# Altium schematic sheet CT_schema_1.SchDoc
size 471 x 395 mm
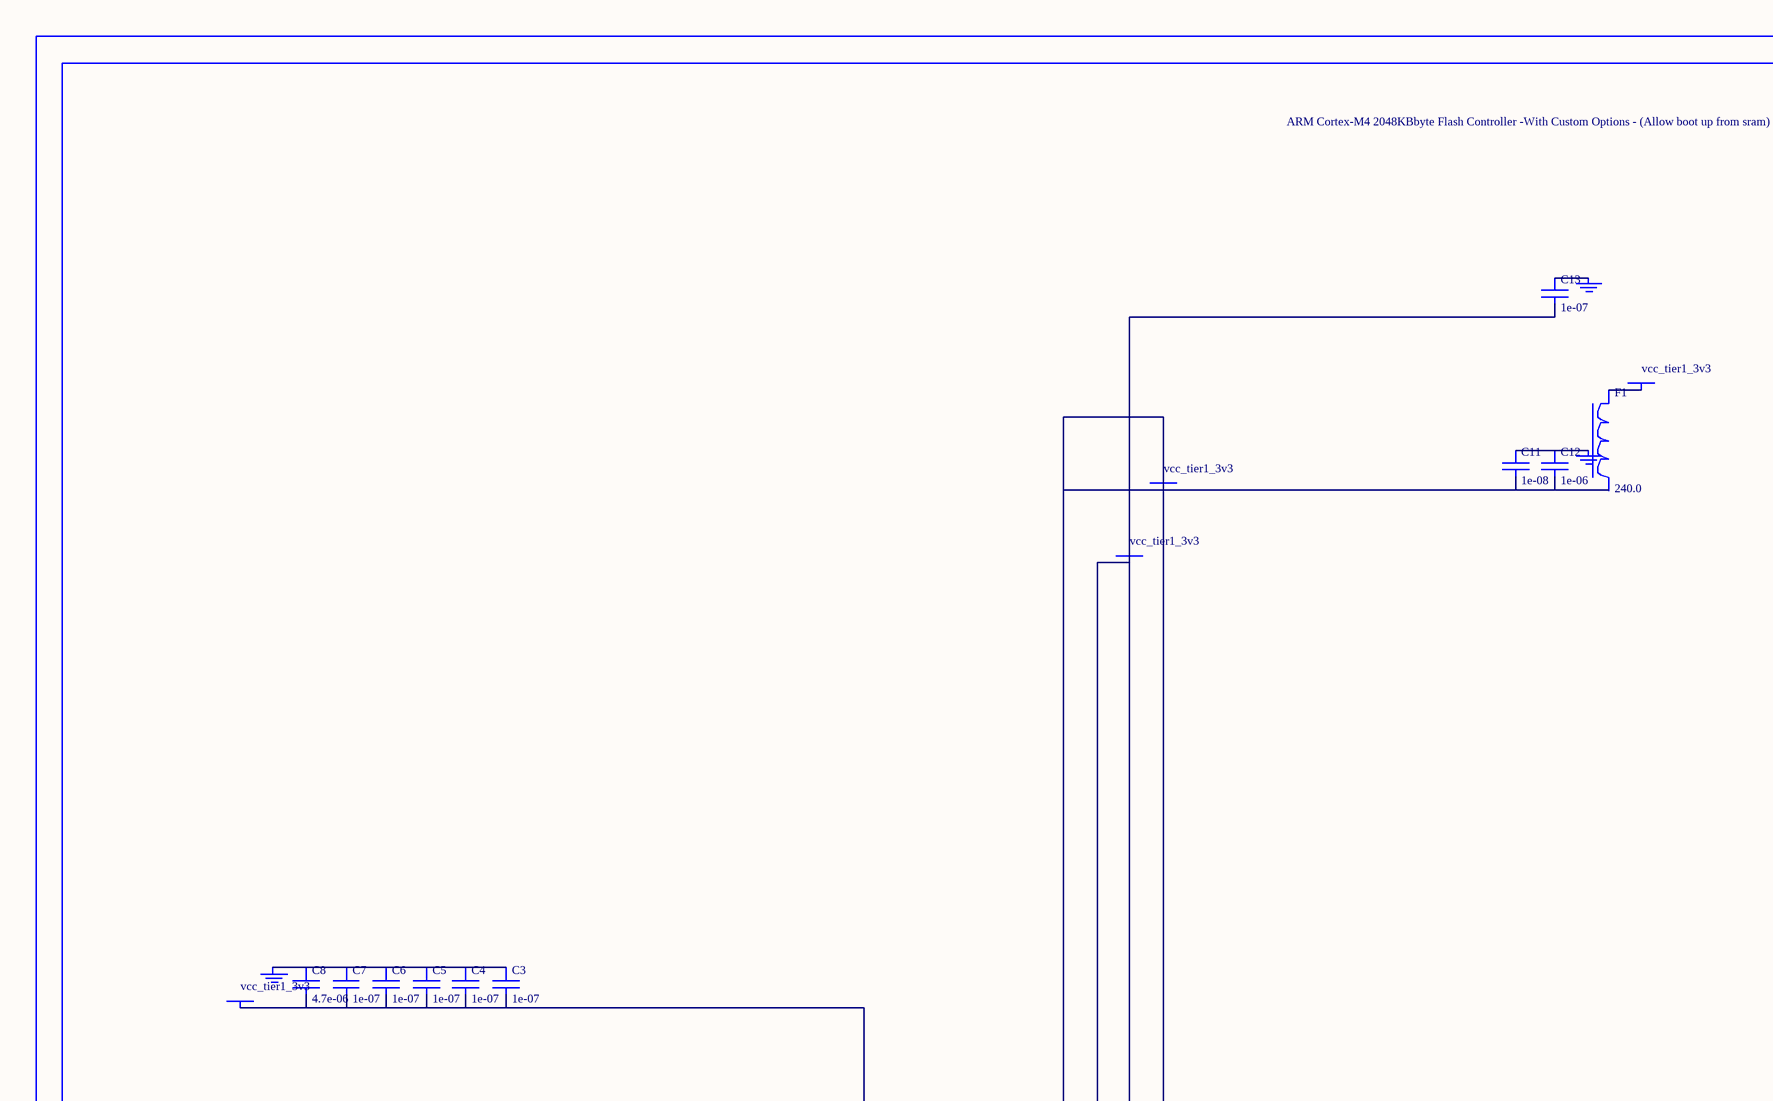
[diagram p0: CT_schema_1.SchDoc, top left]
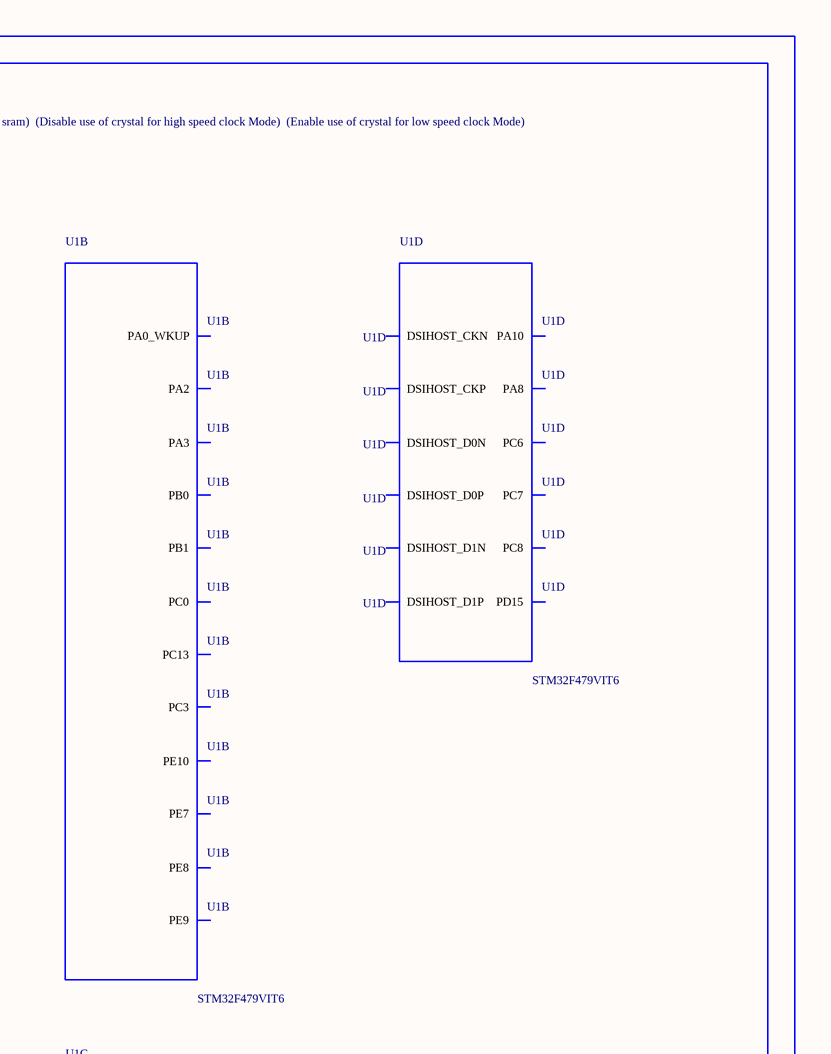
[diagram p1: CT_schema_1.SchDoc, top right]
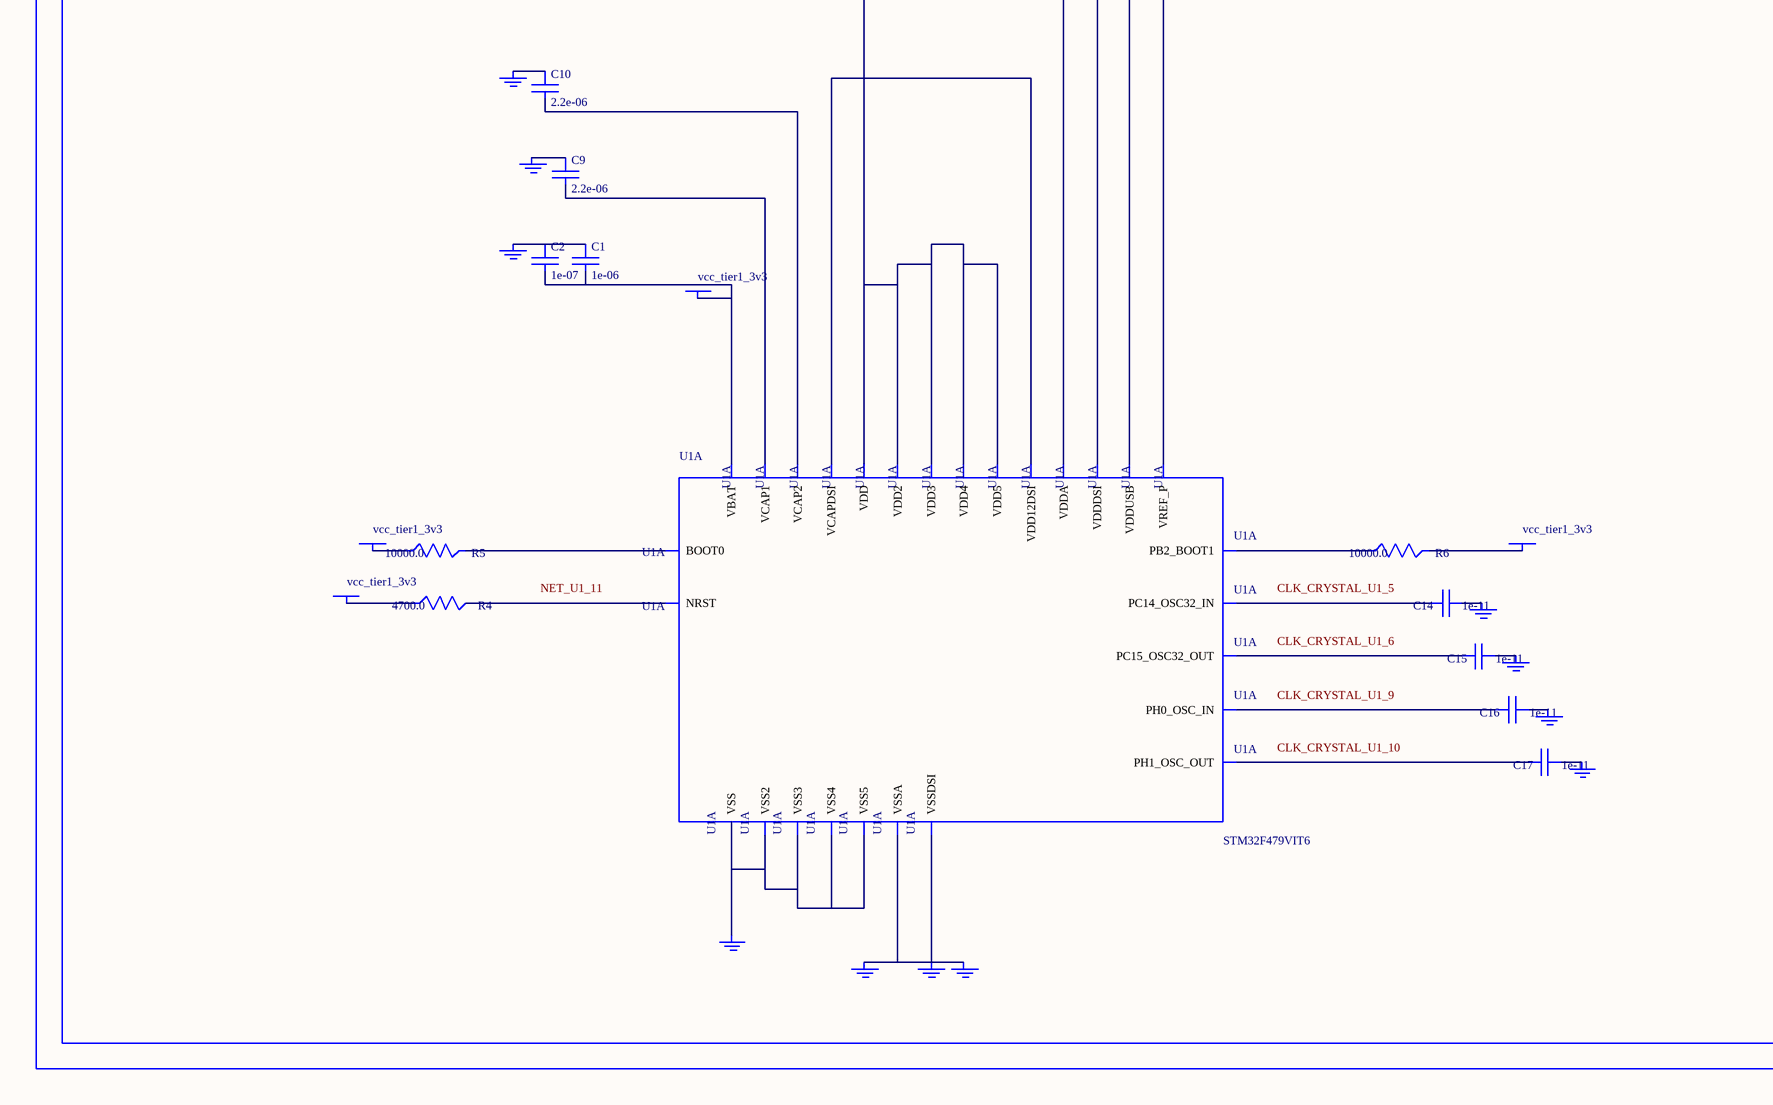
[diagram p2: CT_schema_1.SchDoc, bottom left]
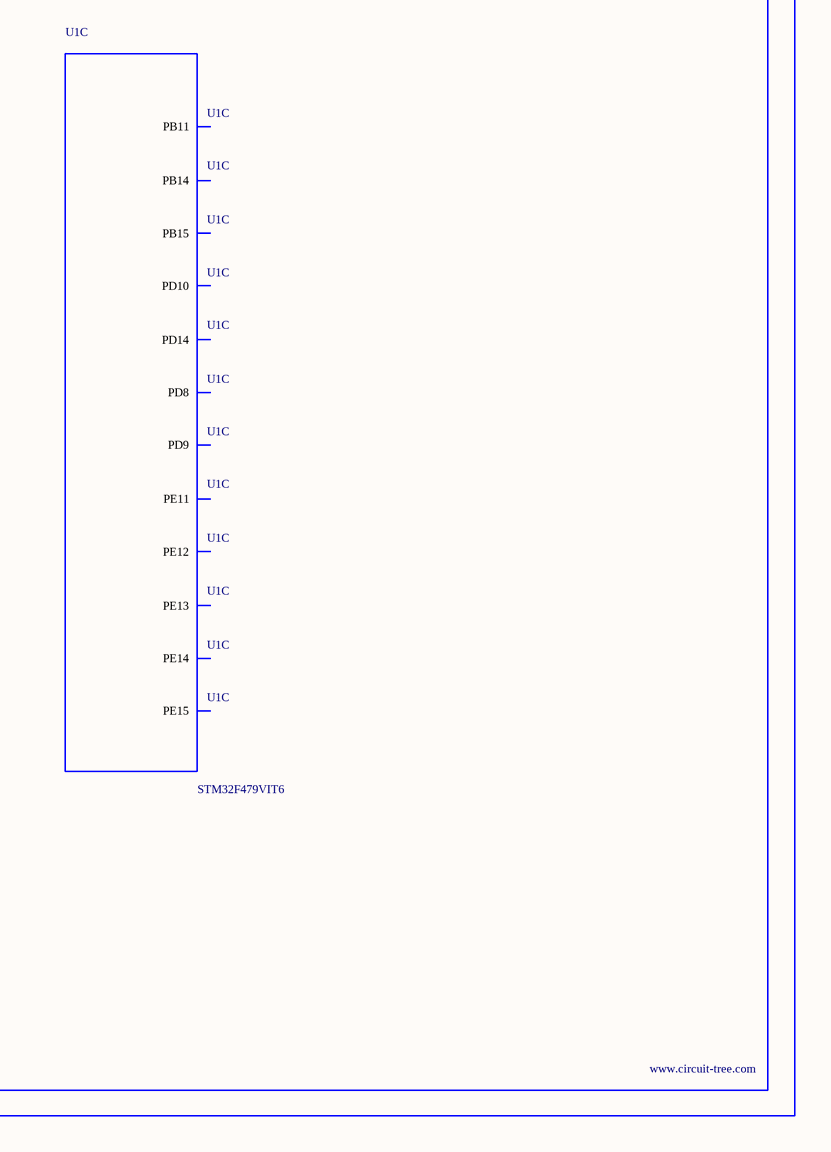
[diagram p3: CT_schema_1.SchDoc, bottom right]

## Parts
BORDER0  (no value)
C1  1e-06  [C0603]
C2  1e-07  [C0603]
C3  1e-07  [C0603]
C4  1e-07  [C0603]
C5  1e-07  [C0603]
C6  1e-07  [C0603]
C7  1e-07  [C0603]
C8  4.7e-06  [C0603]
C9  2.2e-06  [C0603]
C10  2.2e-06  [C0603]
C11  1e-08  [C0603]
C12  1e-06  [C0603]
C13  1e-07  [C0603]
C14  1e-11  [C0402]
C15  1e-11  [C0402]
C16  1e-11  [C0402]
C17  1e-11  [C0402]
F1  240.0  [L0603]
GND_INSTANCE_0_0  (no value)
GND_INSTANCE_0_1  (no value)
GND_INSTANCE_0_2  (no value)
GND_INSTANCE_0_3  (no value)
GND_INSTANCE_0_4  (no value)
GND_INSTANCE_0_5  (no value)
GND_INSTANCE_0_6  (no value)
GND_INSTANCE_0_7  (no value)
GND_INSTANCE_0_8  (no value)
GND_INSTANCE_0_9  (no value)
GND_INSTANCE_0_10  (no value)
GND_INSTANCE_0_11  (no value)
GND_INSTANCE_0_12  (no value)
GND_INSTANCE_0_13  (no value)
POWER_INSTANCE_0_0  vcc_tier1_3v3
POWER_INSTANCE_0_1  vcc_tier1_3v3
POWER_INSTANCE_0_2  vcc_tier1_3v3
POWER_INSTANCE_0_3  vcc_tier1_3v3
POWER_INSTANCE_0_4  vcc_tier1_3v3
POWER_INSTANCE_0_5  vcc_tier1_3v3
POWER_INSTANCE_0_6  vcc_tier1_3v3
POWER_INSTANCE_0_7  vcc_tier1_3v3
R4  4700.0  [R0603]
R5  10000.0  [R0603]
R6  10000.0  [R0603]
U1  STM32F479VIT6  [LQFP100]  (parts A,B,C,D of 9)

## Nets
NetC1_1: C1.1 C2.1 GND_INSTANCE_0_0.0(GND)
NetC1_2: C1.2 C2.2 POWER_INSTANCE_0_0.0(PWR) U1.3(VBAT)
NetC3_1: C3.1 C4.1 C5.1 C6.1 C7.1 C8.1 GND_INSTANCE_0_3.0(GND)
NetC3_2: C3.2 C4.2 C5.2 C6.2 C7.2 C8.2 POWER_INSTANCE_0_1.0(PWR) U1.8(VDD) U1.24(VDD2) U1.45(VDD3) U1.77(VDD4) U1.100(VDD5)
NetC9_1: C9.1 GND_INSTANCE_0_8.0(GND)
NetC9_2: C9.2 U1.43(VCAP1)
NetC10_1: C10.1 GND_INSTANCE_0_12.0(GND)
NetC10_2: C10.2 U1.76(VCAP2)
NetC11_1: C11.1 C12.1 GND_INSTANCE_0_7.0(GND)
NetC11_2: C11.2 C12.2 C13.2 POWER_INSTANCE_0_4.0(PWR) POWER_INSTANCE_0_5.0(PWR) U1.17(VREF_P) U1.18(VDDA) U1.55(VDDDSI) U1.65(VDDUSB)
NetC13_1: C13.1 GND_INSTANCE_0_11.0(GND)
NetC14_1: C14.1 GND_INSTANCE_0_1.0(GND)
NetC14_2: C14.2 U1.5(PC14_OSC32_IN)
NetC15_1: C15.1 GND_INSTANCE_0_2.0(GND)
NetC15_2: C15.2 U1.6(PC15_OSC32_OUT)
NetC16_1: C16.1 GND_INSTANCE_0_4.0(GND)
NetC16_2: C16.2 U1.9(PH0_OSC_IN)
NetC17_1: C17.1 GND_INSTANCE_0_5.0(GND)
NetC17_2: C17.2 U1.10(PH1_OSC_OUT)
NetF1_1: F1.1 POWER_INSTANCE_0_2.0(PWR)
NetGND_INSTANCE_0_6_0: GND_INSTANCE_0_6.0(GND) GND_INSTANCE_0_9.0(GND) GND_INSTANCE_0_10.0(GND) U1.16(VSSA) U1.59(VSSDSI)
NetGND_INSTANCE_0_13_0: GND_INSTANCE_0_13.0(GND) U1.2(VSS) U1.7(VSS2) U1.23(VSS3) U1.44(VSS4) U1.78(VSS5)
NetPOWER_INSTANCE_0_3_0: POWER_INSTANCE_0_3.0(PWR) R6.2
NetPOWER_INSTANCE_0_6_0: POWER_INSTANCE_0_6.0(PWR) R5.1
NetPOWER_INSTANCE_0_7_0: POWER_INSTANCE_0_7.0(PWR) R4.1
NetR4_2: R4.2 U1.11(NRST)
NetR5_2: R5.2 U1.97(BOOT0)
NetR6_1: R6.1 U1.31(PB2_BOOT1)
NetU1_56: U1.56(VCAPDSI) U1.62(VDD12DSI)

Not connected (* = marked no-connect by the designer): F1 2; U1 4(PC13) 12(PC0) 15(PC3) 19(PA0_WKUP) 21(PA2) 22(PA3) 29(PB0) 30(PB1) 32(PE7) 33(PE8) 34(PE9) 35(PE10) 36(PE11) 37(PE12) 38(PE13) 39(PE14) 40(PE15) 42(PB11) 48(PB14) 49(PB15) 50(PD8) 51(PD9) 52(PD10) 53(PD14) 54(PD15) 57(DSIHOST_D0P) 58(DSIHOST_D0N) 60(DSIHOST_CKP) 61(DSIHOST_CKN) 63(DSIHOST_D1P) 64(DSIHOST_D1N) 66(PC6) 67(PC7) 68(PC8) 70(PA8) 72(PA10)

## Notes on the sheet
- Labels drawn without touching a wire or pin: CLK_CRYSTAL_U1_5, CLK_CRYSTAL_U1_6, CLK_CRYSTAL_U1_9, CLK_CRYSTAL_U1_10, NET_U1_11

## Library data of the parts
BORDER0 = BORDER_PAGE0
C1 C12 = C0603C105K3RACTU
C2-C7 C13 = 06035C104K4Z2A
C8 = GRM188R6YA475KE15D
C9 C10 = C0603C225K8RACTU
C11 = 06035C103K4Z2A
C14-C17 = C0402C100K3GACTU
F1 = Z0603C241ASMST
GND_INSTANCE_0_0-GND_INSTANCE_0_13 = GND
POWER_INSTANCE_0_0-POWER_INSTANCE_0_7 = PWR
R4 = RC0603JR-074K7L
R5 R6 = RC0603JR-0710KL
